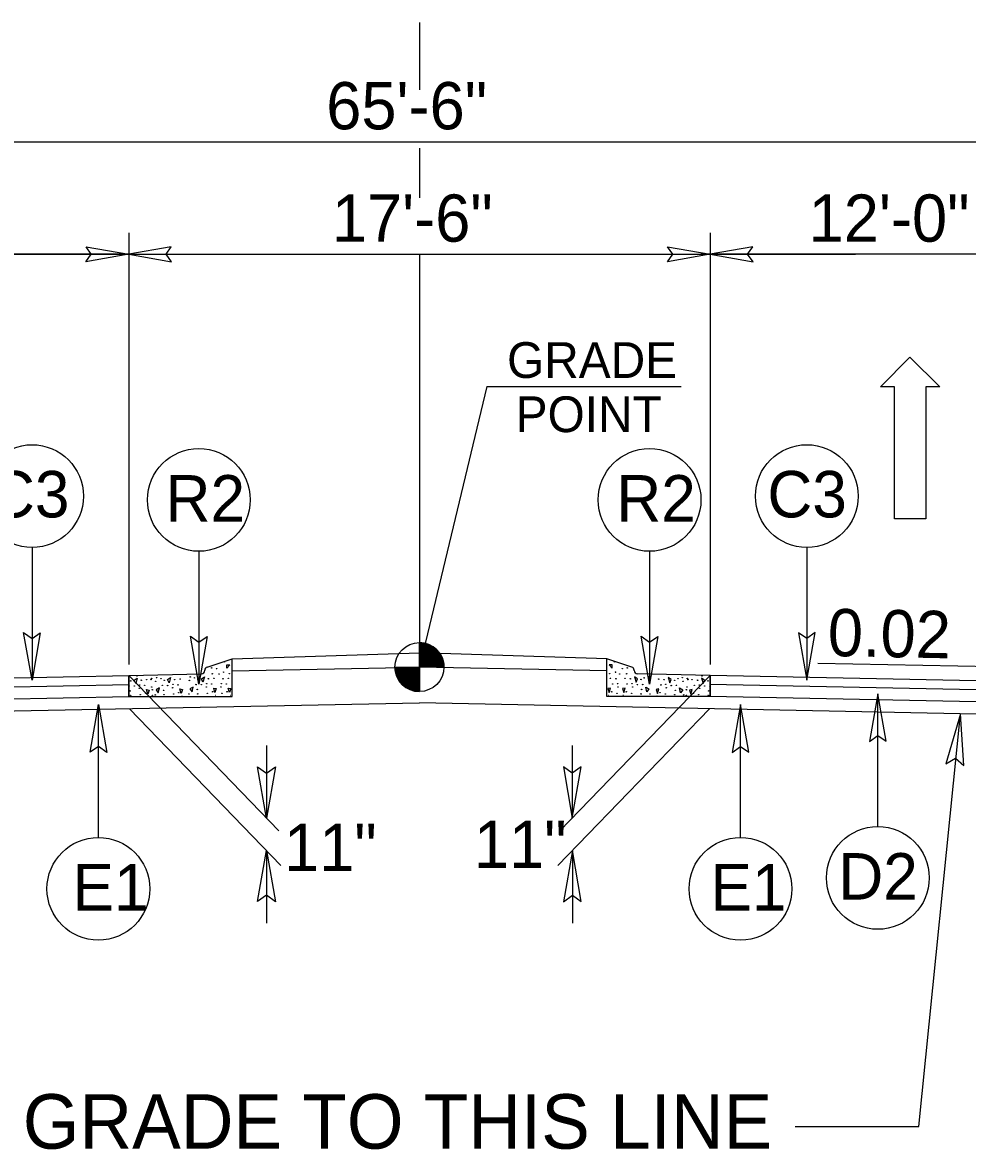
# Model space of a CAD drawing. Extents: x 1904401 to 1905163, y 193929 to 194736.
# Drawn here: x 1904972.98 to 1904998.98, y 194524.24 to 194555.25 of the extents above; entities that cross this region are included whole.
import ezdxf

# ---------------------------------------------------------------- set-up
doc = ezdxf.new("R2010")
doc.units = 0
for name, color, linetype in [('Default', 7, 'Continuous'), ('Old_Level_1', 7, 'Continuous'), ('Old_Level_11', 7, 'Continuous'), ('Old_Level_20', 7, 'Continuous'), ('Old_Level_3', 7, 'Continuous'), ('Prop Dimension Text', 7, 'Continuous'), ('Prop Lane Arrow CELL', 7, 'Continuous'), ('Typical Arrow Superelevation CELL', 7, 'Continuous'), ('Typical Curb CELL', 7, 'Continuous'), ('Typical Pavement Slope CELL', 7, 'Continuous'), ('Typical Terminator CELL', 7, 'Continuous'), ('Typical Text Centerline CELL', 7, 'Continuous')]:
    doc.layers.add(name, color=color, linetype=linetype)

# ---------------------------------------------------------------- blocks, each defined once
blk = doc.blocks.new('TERMINATOR')
at = {"layer": 'Typical Terminator CELL'}
blk.add_lwpolyline([(-0.469, 0.081), (0, 0), (-0.471, -0.083), (-0.411, 0)], close=True, dxfattribs=at)

msp = doc.modelspace()

# ---------------------------------------------------------------- linework, layer by layer
at = {"layer": 'Default'}
for p, q in [((1904975.899, 194549.463), (1904975.899, 194537.59)), ((1904991.899, 194549.463), (1904991.899, 194537.59))]:
    msp.add_line(p, q, dxfattribs=at)
at = {"layer": 'Old_Level_1'}
for p, q in [((1904952.149, 194551.972), (1905015.649, 194551.972)), ((1904964.149, 194548.88), (1904976.149, 194548.88)), ((1904975.899, 194548.88), (1904971.899, 194548.88)), ((1904975.899, 194548.88), (1904991.899, 194548.88)), ((1905003.649, 194548.88), (1904991.649, 194548.88)), ((1904983.899, 194537.518), (1904983.899, 194538.193)), ((1904983.224, 194537.518), (1904983.899, 194537.518)), ((1904983.898, 194536.843), (1904983.899, 194537.518)), ((1904983.899, 194537.518), (1904983.898, 194536.843)), ((1904984.574, 194537.518), (1904983.899, 194537.518)), ((1904975.899, 194537.282), (1904980.033, 194533.012)), ((1904991.899, 194537.282), (1904987.766, 194533.012)), ((1904975.918, 194536.366), (1904980.09, 194532.056)), ((1904991.881, 194536.366), (1904987.709, 194532.056)), ((1904979.694, 194535.362), (1904979.694, 194533.362)), ((1904988.105, 194535.362), (1904988.105, 194533.362)), ((1904979.689, 194532.469), (1904979.689, 194530.469)), ((1904988.11, 194532.469), (1904988.11, 194530.469))]:
    msp.add_line(p, q, dxfattribs=at)
for points in [[(1904983.905, 194538.193), (1904983.905, 194538.193), (1904983.905, 194537.518)], [(1904983.919, 194538.193), (1904983.919, 194537.518)], [(1904983.932, 194538.192), (1904983.932, 194537.518)], [(1904983.946, 194538.192), (1904983.946, 194537.518)], [(1904983.959, 194538.19), (1904983.959, 194537.518)], [(1904983.973, 194538.189), (1904983.973, 194537.518)], [(1904983.986, 194538.187), (1904983.986, 194537.518)], [(1904984, 194538.186), (1904984, 194537.518)], [(1904984.013, 194538.184), (1904984.013, 194537.518)], [(1904984.027, 194538.181), (1904984.027, 194537.518)], [(1904984.04, 194538.178), (1904984.04, 194537.518)], [(1904984.054, 194538.175), (1904984.054, 194537.518)], [(1904984.067, 194538.172), (1904984.067, 194537.518)], [(1904984.081, 194538.168), (1904984.081, 194537.518)], [(1904984.094, 194538.165), (1904984.094, 194537.518)], [(1904984.108, 194538.16), (1904984.108, 194537.518)], [(1904984.121, 194538.156), (1904984.121, 194537.518)], [(1904984.135, 194538.151), (1904984.135, 194537.518)], [(1904984.148, 194538.145), (1904984.148, 194537.518)], [(1904984.162, 194538.139), (1904984.162, 194537.518)], [(1904984.175, 194538.133), (1904984.175, 194537.518)], [(1904984.189, 194538.127), (1904984.189, 194537.518)], [(1904984.202, 194538.121), (1904984.202, 194537.518)], [(1904984.216, 194538.114), (1904984.216, 194537.518)], [(1904984.229, 194538.106), (1904984.229, 194537.518)], [(1904984.243, 194538.099), (1904984.243, 194537.518)], [(1904984.256, 194538.091), (1904984.256, 194537.518)], [(1904984.27, 194538.082), (1904984.27, 194537.518)], [(1904984.283, 194538.073), (1904984.283, 194537.518)], [(1904984.297, 194538.063), (1904984.297, 194537.518)], [(1904984.31, 194538.054), (1904984.31, 194537.518)], [(1904984.324, 194538.043), (1904984.324, 194537.518)], [(1904984.337, 194538.031), (1904984.337, 194537.518)], [(1904984.351, 194538.019), (1904984.351, 194537.518)], [(1904984.364, 194538.007), (1904984.364, 194537.518)], [(1904984.378, 194537.994), (1904984.378, 194537.518)], [(1904984.391, 194537.98), (1904984.391, 194537.518)], [(1904984.405, 194537.965), (1904984.405, 194537.518)], [(1904984.418, 194537.949), (1904984.418, 194537.518)], [(1904984.432, 194537.932), (1904984.432, 194537.518)], [(1904984.445, 194537.914), (1904984.445, 194537.518)], [(1904984.459, 194537.895), (1904984.459, 194537.518)], [(1904984.472, 194537.874), (1904984.472, 194537.518)], [(1904984.486, 194537.851), (1904984.486, 194537.518)], [(1904984.499, 194537.827), (1904984.499, 194537.518)], [(1904984.513, 194537.799), (1904984.513, 194537.518)], [(1904984.526, 194537.767), (1904984.526, 194537.518)], [(1904984.54, 194537.73), (1904984.54, 194537.518)], [(1904983.227, 194537.518), (1904983.227, 194537.445)], [(1904983.241, 194537.518), (1904983.241, 194537.365)], [(1904983.254, 194537.518), (1904983.254, 194537.317)], [(1904983.268, 194537.518), (1904983.268, 194537.277)], [(1904983.281, 194537.518), (1904983.281, 194537.245)], [(1904983.295, 194537.518), (1904983.295, 194537.217)], [(1904983.308, 194537.518), (1904983.308, 194537.191)], [(1904983.322, 194537.518), (1904983.322, 194537.167)], [(1904983.335, 194537.518), (1904983.335, 194537.146)], [(1904983.349, 194537.518), (1904983.349, 194537.127)], [(1904983.362, 194537.518), (1904983.362, 194537.109)], [(1904983.376, 194537.518), (1904983.376, 194537.092)], [(1904983.389, 194537.518), (1904983.389, 194537.076)], [(1904983.403, 194537.518), (1904983.403, 194537.061)], [(1904983.416, 194537.518), (1904983.416, 194537.046)], [(1904983.43, 194537.518), (1904983.43, 194537.032)], [(1904983.443, 194537.518), (1904983.443, 194537.02)], [(1904983.457, 194537.518), (1904983.457, 194537.008)], [(1904983.47, 194537.518), (1904983.47, 194536.996)], [(1904983.484, 194537.518), (1904983.484, 194536.986)], [(1904983.497, 194537.518), (1904983.497, 194536.975)], [(1904983.511, 194537.518), (1904983.511, 194536.966)], [(1904983.524, 194537.518), (1904983.524, 194536.957)], [(1904983.538, 194537.518), (1904983.538, 194536.948)], [(1904983.551, 194537.518), (1904983.551, 194536.939)], [(1904983.565, 194537.518), (1904983.565, 194536.932)], [(1904983.578, 194537.518), (1904983.578, 194536.924)], [(1904983.592, 194537.518), (1904983.592, 194536.917)], [(1904983.605, 194537.518), (1904983.605, 194536.911)], [(1904983.619, 194537.518), (1904983.619, 194536.905)], [(1904983.632, 194537.518), (1904983.632, 194536.899)], [(1904983.646, 194537.518), (1904983.646, 194536.893)], [(1904983.659, 194537.518), (1904983.659, 194536.887)], [(1904983.673, 194537.518), (1904983.673, 194536.882)], [(1904983.686, 194537.518), (1904983.686, 194536.878)], [(1904983.7, 194537.518), (1904983.7, 194536.873)], [(1904983.713, 194537.518), (1904983.713, 194536.87)], [(1904983.727, 194537.518), (1904983.727, 194536.866)], [(1904983.74, 194537.518), (1904983.74, 194536.863)], [(1904983.754, 194537.518), (1904983.754, 194536.86)], [(1904983.767, 194537.518), (1904983.767, 194536.857)], [(1904983.781, 194537.518), (1904983.781, 194536.854)], [(1904983.794, 194537.518), (1904983.794, 194536.852)], [(1904983.808, 194537.518), (1904983.808, 194536.849)], [(1904983.821, 194537.518), (1904983.821, 194536.848)], [(1904983.835, 194537.518), (1904983.835, 194536.846)], [(1904983.848, 194537.518), (1904983.848, 194536.845)], [(1904983.862, 194537.518), (1904983.862, 194536.845)], [(1904983.875, 194537.518), (1904983.875, 194536.843)], [(1904983.889, 194537.518), (1904983.889, 194536.843), (1904983.889, 194536.843)], [(1904984.553, 194537.683), (1904984.553, 194537.518)], [(1904984.567, 194537.614), (1904984.567, 194537.518)]]:
    msp.add_lwpolyline(points, dxfattribs=at)
msp.add_circle((1904983.899, 194537.518), 0.675, dxfattribs=at)
for start, end in [(359.9905, 89.9905), (179.9905, 269.9905)]:
    msp.add_arc((1904983.899, 194537.518), 0.675, start, end, dxfattribs=at)
at = {"layer": 'Old_Level_11'}
for p, q in [((1904973.24, 194540.807), (1904973.24, 194537.153)), ((1904977.83, 194540.704), (1904977.83, 194537.05)), ((1904990.232, 194540.704), (1904990.232, 194537.05)), ((1904994.559, 194540.807), (1904994.559, 194537.153)), ((1904975.065, 194532.829), (1904975.065, 194536.484)), ((1904992.734, 194532.829), (1904992.734, 194536.484)), ((1904996.513, 194533.13), (1904996.513, 194536.784))]:
    msp.add_line(p, q, dxfattribs=at)
for points in [[(1904973.465, 194538.463), (1904973.24, 194537.153), (1904973.007, 194538.469), (1904973.24, 194538.302)], [(1904978.055, 194538.359), (1904977.83, 194537.05), (1904977.597, 194538.366), (1904977.83, 194538.199)], [(1904990.457, 194538.359), (1904990.232, 194537.05), (1904989.999, 194538.366), (1904990.232, 194538.199)], [(1904994.334, 194538.463), (1904994.559, 194537.153), (1904994.792, 194538.469), (1904994.559, 194538.302)], [(1904974.839, 194535.174), (1904975.065, 194536.484), (1904975.298, 194535.168), (1904975.065, 194535.335)], [(1904992.959, 194535.174), (1904992.734, 194536.484), (1904992.501, 194535.168), (1904992.734, 194535.335)], [(1904996.738, 194535.475), (1904996.513, 194536.784), (1904996.28, 194535.468), (1904996.513, 194535.635)]]:
    msp.add_lwpolyline(points, close=True, dxfattribs=at)
for centre in [(1904973.24, 194542.222), (1904994.559, 194542.222), (1904977.83, 194542.118), (1904990.232, 194542.118), (1904996.513, 194531.715), (1904975.065, 194531.415), (1904992.734, 194531.415)]:
    msp.add_circle(centre, 1.414, dxfattribs=at)
at = {"layer": 'Old_Level_3'}
for q in [(1904983.899, 194537.518), (1904991.097, 194545.237)]:
    msp.add_line((1904985.751, 194545.237), q, dxfattribs=at)
at = {"layer": 'Prop Dimension Text'}
for p, q in [((1904964.899, 194548.88), (1904975.899, 194548.88)), ((1905002.899, 194548.88), (1904991.899, 194548.88)), ((1904991.899, 194548.88), (1904995.899, 194548.88))]:
    msp.add_line(p, q, dxfattribs=at)
at = {"layer": 'Prop Lane Arrow CELL'}
for p, q in [((1904996.585, 194545.232), (1904997.389, 194546.049)), ((1904997.389, 194546.049), (1904998.219, 194545.232)), ((1904996.974, 194545.232), (1904996.585, 194545.232)), ((1904996.974, 194541.601), (1904996.974, 194545.232)), ((1904998.219, 194545.232), (1904997.83, 194545.232)), ((1904997.83, 194545.232), (1904997.83, 194541.601)), ((1904997.83, 194541.601), (1904996.974, 194541.601)), ((1904997.64, 194524.87), (1904998.789, 194536.234)), ((1904994.241, 194524.87), (1904997.64, 194524.87))]:
    msp.add_line(p, q, dxfattribs=at)
at = {"layer": 'Typical Arrow Superelevation CELL'}
msp.add_line((1904999.935, 194537.518), (1904994.864, 194537.619), dxfattribs=at)
at = {"layer": 'Typical Curb CELL'}
for p, q in [((1904978.057, 194537.519), (1904978.743, 194537.748)), ((1904978.743, 194536.705), (1904978.743, 194537.748)), ((1904989.056, 194536.705), (1904989.056, 194537.748)), ((1904989.742, 194537.519), (1904989.056, 194537.748)), ((1904977.993, 194537.425), (1904977.993, 194537.43)), ((1904978.596, 194537.576), (1904978.682, 194537.576)), ((1904978.601, 194537.49), (1904978.596, 194537.576)), ((1904978.682, 194537.576), (1904978.601, 194537.49)), ((1904989.203, 194537.576), (1904989.117, 194537.576)), ((1904989.117, 194537.576), (1904989.198, 194537.49)), ((1904989.198, 194537.49), (1904989.203, 194537.576)), ((1904989.806, 194537.425), (1904989.806, 194537.43)), ((1904975.899, 194537.288), (1904977.899, 194537.331)), ((1904975.899, 194537.288), (1904975.899, 194536.705)), ((1904975.899, 194536.705), (1904975.899, 194537.282)), ((1904976.053, 194537.156), (1904976.135, 194537.215)), ((1904976.093, 194537.066), (1904976.053, 194537.156)), ((1904976.135, 194537.215), (1904976.093, 194537.066)), ((1904976.972, 194537.172), (1904977.054, 194537.231)), ((1904977.013, 194537.081), (1904976.972, 194537.172)), ((1904977.054, 194537.231), (1904977.013, 194537.081)), ((1904977.899, 194537.194), (1904977.982, 194537.253)), ((1904977.94, 194537.103), (1904977.899, 194537.194)), ((1904977.982, 194537.253), (1904977.94, 194537.103)), ((1904989.817, 194537.253), (1904989.859, 194537.103)), ((1904989.899, 194537.194), (1904989.817, 194537.253)), ((1904989.859, 194537.103), (1904989.899, 194537.194)), ((1904991.899, 194537.288), (1904989.899, 194537.331)), ((1904990.745, 194537.231), (1904990.786, 194537.081)), ((1904990.827, 194537.172), (1904990.745, 194537.231)), ((1904990.786, 194537.081), (1904990.827, 194537.172)), ((1904991.664, 194537.215), (1904991.706, 194537.066)), ((1904991.746, 194537.156), (1904991.664, 194537.215)), ((1904991.706, 194537.066), (1904991.746, 194537.156)), ((1904991.899, 194537.288), (1904991.899, 194536.705)), ((1904991.899, 194536.705), (1904991.899, 194537.282)), ((1904976.392, 194536.899), (1904976.464, 194536.885)), ((1904976.428, 194536.776), (1904976.392, 194536.899)), ((1904976.464, 194536.885), (1904976.428, 194536.776)), ((1904976.746, 194536.942), (1904976.656, 194536.892)), ((1904976.656, 194536.892), (1904976.715, 194536.811)), ((1904976.715, 194536.811), (1904976.746, 194536.942)), ((1904977.311, 194536.915), (1904977.384, 194536.901)), ((1904977.347, 194536.792), (1904977.311, 194536.915)), ((1904977.384, 194536.901), (1904977.347, 194536.792)), ((1904977.674, 194536.964), (1904977.584, 194536.914)), ((1904977.584, 194536.914), (1904977.642, 194536.833)), ((1904977.642, 194536.833), (1904977.674, 194536.964)), ((1904978.239, 194536.937), (1904978.311, 194536.923)), ((1904978.274, 194536.814), (1904978.239, 194536.937)), ((1904978.311, 194536.923), (1904978.274, 194536.814)), ((1904978.639, 194536.937), (1904978.712, 194536.923)), ((1904978.675, 194536.814), (1904978.639, 194536.937)), ((1904978.712, 194536.923), (1904978.675, 194536.814)), ((1904989.159, 194536.937), (1904989.087, 194536.923)), ((1904989.087, 194536.923), (1904989.124, 194536.814)), ((1904989.124, 194536.814), (1904989.159, 194536.937)), ((1904989.56, 194536.937), (1904989.488, 194536.923)), ((1904989.488, 194536.923), (1904989.524, 194536.814)), ((1904989.524, 194536.814), (1904989.56, 194536.937)), ((1904990.125, 194536.964), (1904990.215, 194536.914)), ((1904990.157, 194536.833), (1904990.125, 194536.964)), ((1904990.215, 194536.914), (1904990.157, 194536.833)), ((1904990.488, 194536.915), (1904990.415, 194536.901)), ((1904990.415, 194536.901), (1904990.452, 194536.792)), ((1904990.452, 194536.792), (1904990.488, 194536.915)), ((1904991.052, 194536.942), (1904991.143, 194536.892)), ((1904991.084, 194536.811), (1904991.052, 194536.942)), ((1904991.143, 194536.892), (1904991.084, 194536.811)), ((1904991.407, 194536.899), (1904991.334, 194536.885)), ((1904991.334, 194536.885), (1904991.371, 194536.776)), ((1904991.371, 194536.776), (1904991.407, 194536.899)), ((1904975.899, 194536.705), (1904978.743, 194536.705)), ((1904991.899, 194536.705), (1904989.056, 194536.705))]:
    msp.add_line(p, q, dxfattribs=at)
for centre in [(1904978.181, 194537.495), (1904978.316, 194537.472), (1904978.533, 194537.662), (1904989.266, 194537.662), (1904989.483, 194537.472), (1904989.618, 194537.495), (1904975.958, 194537.138), (1904976.125, 194537.269), (1904976.247, 194537.156), (1904976.396, 194537.17), (1904976.514, 194537.174), (1904976.529, 194537.203), (1904976.642, 194537.127), (1904976.665, 194537.226), (1904976.787, 194537.199), (1904976.877, 194537.154), (1904977.166, 194537.172), (1904977.316, 194537.185), (1904977.57, 194537.149), (1904977.592, 194537.248), (1904977.714, 194537.221), (1904977.805, 194537.176), (1904978.094, 194537.194), (1904978.199, 194537.332), (1904978.243, 194537.208), (1904978.388, 194537.327), (1904978.495, 194537.194), (1904978.506, 194537.377), (1904978.644, 194537.208), (1904978.668, 194537.336), (1904989.131, 194537.336), (1904989.155, 194537.208), (1904989.293, 194537.377), (1904989.304, 194537.194), (1904989.411, 194537.327), (1904989.556, 194537.208), (1904989.6, 194537.332), (1904989.705, 194537.194), (1904989.994, 194537.176), (1904990.084, 194537.221), (1904990.206, 194537.248), (1904990.229, 194537.149), (1904990.483, 194537.185), (1904990.632, 194537.172), (1904990.922, 194537.154), (1904991.012, 194537.199), (1904991.134, 194537.226), (1904991.156, 194537.127), (1904991.269, 194537.203), (1904991.285, 194537.174), (1904991.402, 194537.17), (1904991.552, 194537.156), (1904991.674, 194537.269), (1904991.841, 194537.138), (1904975.908, 194536.998), (1904975.94, 194536.863), (1904976.053, 194536.994), (1904976.189, 194536.93), (1904976.202, 194537.025), (1904976.338, 194537.012), (1904976.36, 194536.799), (1904976.536, 194536.971), (1904976.552, 194536.892), (1904976.828, 194537.014), (1904976.859, 194536.878), (1904976.972, 194537.009), (1904977.108, 194536.946), (1904977.121, 194537.041), (1904977.257, 194537.027), (1904977.279, 194536.815), (1904977.755, 194537.036), (1904977.787, 194536.901), (1904977.9, 194537.032), (1904978.035, 194536.968), (1904978.049, 194537.063), (1904978.062, 194536.797), (1904978.184, 194537.05), (1904978.207, 194536.837), (1904978.436, 194536.968), (1904978.449, 194537.063), (1904978.463, 194536.797), (1904978.585, 194537.05), (1904978.608, 194536.837), (1904989.191, 194536.837), (1904989.214, 194537.05), (1904989.336, 194536.797), (1904989.35, 194537.063), (1904989.363, 194536.968), (1904989.592, 194536.837), (1904989.615, 194537.05), (1904989.737, 194536.797), (1904989.75, 194537.063), (1904989.764, 194536.968), (1904989.899, 194537.032), (1904990.012, 194536.901), (1904990.044, 194537.036), (1904990.52, 194536.815), (1904990.542, 194537.027), (1904990.678, 194537.041), (1904990.691, 194536.946), (1904990.827, 194537.009), (1904990.94, 194536.878), (1904990.971, 194537.014), (1904991.247, 194536.892), (1904991.263, 194536.971), (1904991.439, 194536.799), (1904991.461, 194537.012), (1904991.597, 194537.025), (1904991.61, 194536.93), (1904991.746, 194536.994), (1904991.859, 194536.863), (1904991.89, 194536.998), (1904975.954, 194536.741), (1904976.216, 194536.759), (1904976.552, 194536.738), (1904976.629, 194536.752), (1904976.873, 194536.756), (1904977.135, 194536.774), (1904977.556, 194536.774), (1904977.8, 194536.779), (1904989.999, 194536.779), (1904990.243, 194536.774), (1904990.664, 194536.774), (1904990.926, 194536.756), (1904991.17, 194536.752), (1904991.247, 194536.738), (1904991.583, 194536.759), (1904991.845, 194536.741)]:
    msp.add_circle(centre, 0.00635, dxfattribs=at)
for centre, radius, start, end in [((1904977.899, 194537.425), 0.0937, 270, 0), ((1904978.087, 194537.43), 0.0937, 108.435, 180), ((1904989.712, 194537.43), 0.0937, 360, 71.565), ((1904989.899, 194537.425), 0.0937, 180, 270), ((1904977.365, 194536.711), 0.00635, 25.7584, 152.9614), ((1904978.293, 194536.733), 0.00635, 25.7584, 152.9614), ((1904978.693, 194536.733), 0.00635, 25.7584, 152.9614), ((1904989.106, 194536.733), 0.00635, 27.0386, 154.2416), ((1904989.506, 194536.733), 0.00635, 27.0386, 154.2416), ((1904990.434, 194536.711), 0.00635, 27.0386, 154.2416)]:
    msp.add_arc(centre, radius, start, end, dxfattribs=at)
at = {"layer": 'Typical Pavement Slope CELL'}
for p, q in [((1904978.743, 194537.748), (1904983.899, 194537.911)), ((1904989.056, 194537.748), (1904983.899, 194537.911)), ((1904978.743, 194537.415), (1904983.899, 194537.518)), ((1904989.056, 194537.415), (1904983.899, 194537.518)), ((1904964.149, 194537.053), (1904975.899, 194537.288)), ((1905003.649, 194537.053), (1904991.899, 194537.288)), ((1904964.149, 194536.803), (1904975.899, 194537.038)), ((1905003.649, 194536.803), (1904991.894, 194537.038)), ((1904960.759, 194536.069), (1904983.899, 194536.531)), ((1904964.149, 194536.47), (1904975.899, 194536.705)), ((1905007.04, 194536.069), (1904983.899, 194536.532)), ((1905003.649, 194536.47), (1904991.888, 194536.705))]:
    msp.add_line(p, q, dxfattribs=at)
at = {"layer": 'Typical Terminator CELL'}
for points in [[(1904974.728, 194549.081), (1904975.899, 194548.88), (1904974.721, 194548.671), (1904974.871, 194548.88)], [(1904977.071, 194549.081), (1904975.899, 194548.88), (1904977.078, 194548.671), (1904976.928, 194548.88)], [(1904990.728, 194549.081), (1904991.899, 194548.88), (1904990.721, 194548.671), (1904990.871, 194548.88)], [(1904993.071, 194549.081), (1904991.899, 194548.88), (1904993.078, 194548.671), (1904992.928, 194548.88)], [(1904998.876, 194534.81), (1904998.789, 194536.234), (1904998.386, 194534.856), (1904998.654, 194535.007)]]:
    msp.add_lwpolyline(points, close=True, dxfattribs=at)
at = {"layer": 'Typical Text Centerline CELL'}
for p, q in [((1904983.899, 194555.255), (1904983.899, 194553.407)), ((1904983.899, 194551.8), (1904983.899, 194550.431)), ((1904983.899, 194548.88), (1904983.899, 194537.518))]:
    msp.add_line(p, q, dxfattribs=at)

# ---------------------------------------------------------------- block references
at = {"layer": 'Old_Level_1', "xscale": 3}
for p, yscale, rotation in [((1904979.694, 194533.362), 3, -90), ((1904988.105, 194533.362), -3, -90.00000000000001), ((1904979.689, 194532.469), 3, 90), ((1904988.11, 194532.469), -3, 90)]:
    msp.add_blockref('TERMINATOR', p, dxfattribs=dict(at, yscale=yscale, rotation=rotation))

# ---------------------------------------------------------------- texts
at = {"layer": 'Old_Level_1'}
for s, p in [('65\'-6"', (1904981.335, 194552.316)), ('17\'-6"', (1904981.49, 194549.223)), ('12\'-0"', (1904994.608, 194549.223))]:
    msp.add_text(s, height=1.3, dxfattribs=at).set_placement(p)
at = {"layer": 'Old_Level_11'}
for s, p in [('GRADE', (1904986.31, 194545.474)), ('POINT', (1904986.547, 194543.983))]:
    msp.add_text(s, height=0.984, dxfattribs=at).set_placement(p)
at = {"layer": 'Old_Level_20'}
for s, height, p in [('C3', 1.2792, (1904972.083, 194541.636)), ('R2', 1.2792, (1904976.915, 194541.521)), ('R2', 1.2792, (1904989.317, 194541.521)), ('C3', 1.2792, (1904993.474, 194541.636)), ('11"', 1.3, (1904980.174, 194531.906)), ('11"', 1.3, (1904985.398, 194531.99)), ('D2', 1.2792, (1904995.426, 194531.118)), ('E1', 1.2792, (1904974.356, 194530.818)), ('E1', 1.2792, (1904991.907, 194530.818))]:
    msp.add_text(s, height=height, dxfattribs=at).set_placement(p)
at = {"layer": 'Prop Dimension Text'}
msp.add_text('0.02', height=1.3, rotation=358.8538, dxfattribs=at).set_placement((1904995.126, 194537.824))
at = {"layer": 'Prop Lane Arrow CELL'}
msp.add_text('GRADE TO THIS LINE', height=1.5, rotation=0.0002, dxfattribs=at).set_placement((1904972.986, 194524.263))

doc.saveas('drawing.dxf')
